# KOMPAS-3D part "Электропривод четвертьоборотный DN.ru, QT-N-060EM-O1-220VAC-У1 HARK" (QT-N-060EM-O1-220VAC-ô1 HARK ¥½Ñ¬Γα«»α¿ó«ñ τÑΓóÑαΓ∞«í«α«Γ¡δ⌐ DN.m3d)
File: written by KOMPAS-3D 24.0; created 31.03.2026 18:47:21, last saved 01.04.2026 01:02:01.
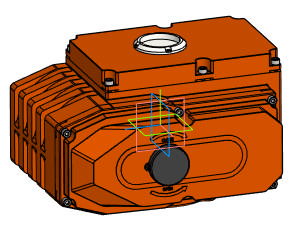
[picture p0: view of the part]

Document properties: Автор: DN.RU; Полное имя файла: D:\PROJECT CAD\DN.RU\...195\Исходники\220В\QT-N-060EM-O1-220VAC-У1 HARK Электропривод четвертьоборотный DN.ru\QT-N-060EM-O1-220VAC-У1 HARK Электропривод четвертьоборотный DN.m3d

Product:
- Body: Твердое тело1  | qty 1
    Масса: 37.407802
- Part/product: Электропривод четвертьоборотный DN.ru  | designation QT-N-060EM-O1-220VAC-У1 HARK
    Масса: 9.3
    Раздел спецификации: Прочие изделия
    Комментарий: D300-05875
    Примечание: D300-05874
    additional columns: Сталь

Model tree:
1. Твердое тело1  (labels: Твердое тело1)

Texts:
  QT-N-060EM-O1-220VAC-У1 HARK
